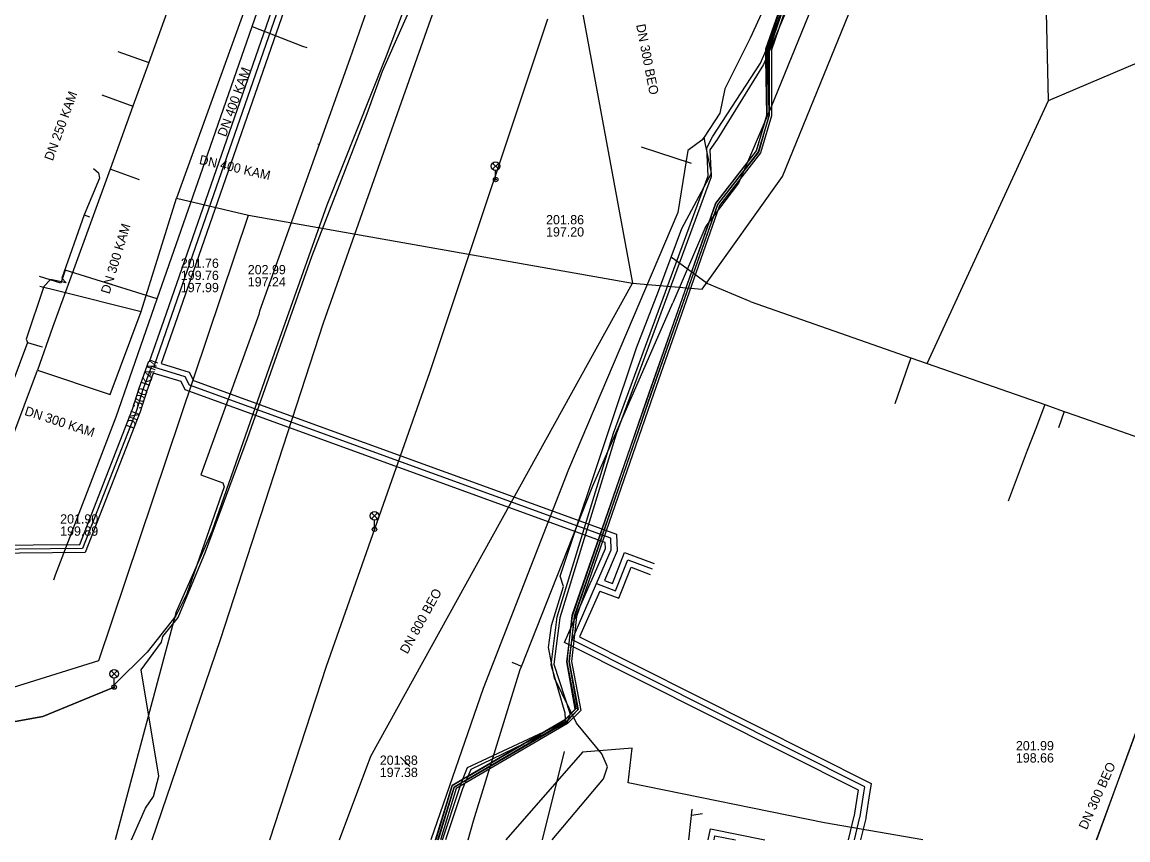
# Model space of a CAD drawing. Extents: x -598932 to -598196, y -1162210 to -1161504.
# Drawn here: x -598647.1 to -598551.8, y -1162207 to -1162136.5 of the extents above; entities that cross this region are included whole.
import ezdxf

# ---------------------------------------------------------------- set-up
doc = ezdxf.new("R2010")
doc.units = 0
for name, color, linetype in [('Vrstva 1', 7, 'Continuous'), ('Vrstva 12', 7, 'Continuous'), ('Vrstva 14', 7, 'Continuous'), ('Vrstva 25', 7, 'Continuous'), ('Vrstva 26', 7, 'Continuous'), ('Vrstva 33', 7, 'Continuous'), ('Vrstva 4', 7, 'Continuous'), ('Vrstva 42', 7, 'Continuous'), ('Vrstva 44', 7, 'Continuous'), ('Vrstva 53', 7, 'Continuous'), ('Vrstva 55', 7, 'Continuous'), ('Vrstva 58', 7, 'Continuous'), ('Vrstva 9', 7, 'Continuous')]:
    doc.layers.add(name, color=color, linetype=linetype)

msp = doc.modelspace()

# ---------------------------------------------------------------- linework, layer by layer
at = {"layer": 'Vrstva 1'}
for p, q in [((-598599.03, -1162134.42), (-598594.47, -1162159.01)), ((-598599.027, -1162134.423), (-598594.47, -1162159.01)), ((-598589.4, -1162148.69), (-598593.72, -1162147.3)), ((-598617.02, -1162199.746), (-598594.47, -1162159.01)), ((-598617.02, -1162199.75), (-598594.47, -1162159.01)), ((-598619.723, -1162206.96), (-598617.02, -1162199.75)), ((-598619.723, -1162206.96), (-598617.02, -1162199.75)), ((-598619.723, -1162206.96), (-598617.02, -1162199.75)), ((-598613.67, -1162200.65), (-598614.45, -1162199.84)), ((-598600.37, -1162199.35), (-598602.252, -1162206.96)), ((-598589.37, -1162204.32), (-598589.653, -1162206.96)), ((-598589.4, -1162204.84), (-598588.45, -1162204.7))]:
    msp.add_line(p, q, dxfattribs=at)
at = {"layer": 'Vrstva 12'}
for p, q in [((-598558.659, -1162143.26), (-598558.872, -1162133.76)), ((-598558.659, -1162143.26), (-598547.642, -1162138.579)), ((-598569.119, -1162165.913), (-598558.659, -1162143.26)), ((-598588.22, -1162146.91), (-598588.32, -1162146.42)), ((-598591.14, -1162156.76), (-598590.22, -1162154.29)), ((-598584.36, -1162160.58), (-598570.51, -1162165.42)), ((-598570.51, -1162165.42), (-598571.9, -1162169.4)), ((-598570.51, -1162165.42), (-598569.119, -1162165.913)), ((-598569.119, -1162165.913), (-598558.98, -1162169.46)), ((-598558.98, -1162169.46), (-598559.702, -1162171.367)), ((-598558.98, -1162169.46), (-598557.3, -1162170.05)), ((-598557.3, -1162170.05), (-598557.8, -1162171.46)), ((-598555.72, -1162170.6), (-598548.21, -1162173.23)), ((-598559.702, -1162171.367), (-598560.493, -1162173.405)), ((-598560.493, -1162173.405), (-598562.125, -1162177.779))]:
    msp.add_line(p, q, dxfattribs=at)
for points in [[(-598564.12, -1162088.67), (-598581.15, -1162130.92), (-598584.34, -1162137.89), (-598586.52, -1162142.25), (-598586.97, -1162144.37), (-598588.32, -1162146.42)], [(-598588.32, -1162146.42), (-598588.5, -1162146.68), (-598589.73, -1162147.56), (-598590.59, -1162152.91), (-598599.99, -1162175.05), (-598607.33, -1162193.91), (-598611.862, -1162206.96)], [(-598590.22, -1162154.29), (-598587.68, -1162149.53), (-598588.22, -1162146.91)], [(-598596.39, -1162171.26), (-598594.15, -1162164.58), (-598592.24, -1162159.7), (-598591.14, -1162156.76)], [(-598584.36, -1162160.58), (-598588.06, -1162159.04), (-598591.14, -1162156.76)], [(-598557.3, -1162170.05), (-598556.312, -1162170.394), (-598555.72, -1162170.6)], [(-598601.73, -1162190.39), (-598601.45, -1162188.5), (-598600.43, -1162185.14), (-598600.72, -1162184.23), (-598596.39, -1162171.26)], [(-598543.01, -1162175.29), (-598543.1, -1162175.61), (-598554.511, -1162206.96)], [(-598601.404, -1162206.96), (-598596.99, -1162201.69), (-598596.64, -1162200.68), (-598597.13, -1162199.54), (-598599.3, -1162196.9), (-598601.2, -1162193.04), (-598601.73, -1162190.39)]]:
    msp.add_lwpolyline(points, dxfattribs=at)
at = {"layer": 'Vrstva 14'}
for p, q in [((-598604.35, -1162191.89), (-598604.846, -1162191.681)), ((-598604.045, -1162192.016), (-598604.35, -1162191.89))]:
    msp.add_line(p, q, dxfattribs=at)
for points in [[(-598644.33, -1162184.57), (-598644.18, -1162184.13), (-598638.95, -1162170.52), (-598635.41, -1162160.34), (-598631.28, -1162148.51), (-598627.24, -1162136.89), (-598622.28, -1162122.66), (-598619.58, -1162114.82), (-598618.34, -1162111.2), (-598616.83, -1162107.09), (-598616.56, -1162106.45), (-598613.65, -1162097.83), (-598610.8, -1162090.29), (-598610.7, -1162090), (-598610.57, -1162089.6)], [(-598564.409, -1162099.249), (-598565.028, -1162100.748), (-598571.148, -1162115.82), (-598576.14, -1162128.127), (-598576.752, -1162129.574), (-598582.543, -1162143.824), (-598585.362, -1162150.375), (-598588.164, -1162154.078), (-598591.021, -1162160.688)], [(-598627.24, -1162136.89), (-598622.89, -1162138.58), (-598622.52, -1162138.7)], [(-598635.41, -1162160.34), (-598643.344, -1162157.87), (-598643.714, -1162159.012), (-598645.55, -1162158.44)], [(-598608.626, -1162206.96), (-598608.18, -1162205.33), (-598604.15, -1162192.28), (-598604.045, -1162192.016), (-598597.9, -1162176.46), (-598591.021, -1162160.688)]]:
    msp.add_lwpolyline(points, dxfattribs=at)
at = {"layer": 'Vrstva 25'}
for points in [[(-598635.714, -1162166.241), (-598634.381, -1162162.409), (-598634.38, -1162162.406), (-598613.829, -1162103.32), (-598624.234, -1162099.93)], [(-598635.714, -1162166.241), (-598635.92, -1162166.167), (-598636.647, -1162168.163), (-598637.21, -1162169.971), (-598641.849, -1162181.867), (-598650.127, -1162181.931), (-598683.649, -1162183.117)], [(-598597.574, -1162184.887), (-598596.314, -1162181.963), (-598596.342, -1162180.979), (-598632.642, -1162167.789), (-598633.001, -1162167.072), (-598635.714, -1162166.241)], [(-598597.574, -1162184.887), (-598595.933, -1162185.508), (-598594.875, -1162182.83), (-598592.782, -1162183.618)], [(-598574.561, -1162202.896), (-598574.475, -1162202.385), (-598599.692, -1162189.716), (-598597.574, -1162184.887)], [(-598575.365, -1162206.96), (-598574.892, -1162205.015), (-598574.88, -1162204.939), (-598574.561, -1162202.896)], [(-598587.457, -1162206.96), (-598587.382, -1162206.608), (-598585.622, -1162206.96)]]:
    msp.add_lwpolyline(points, dxfattribs=at)
at = {"layer": 'Vrstva 26'}
for points in [[(-598624.079, -1162099.455), (-598613.189, -1162103.003), (-598633.909, -1162162.573), (-598635.071, -1162165.915)], [(-598636.07, -1162165.741), (-598634.853, -1162162.244), (-598614.469, -1162103.637), (-598624.389, -1162100.405)], [(-598683.661, -1162182.767), (-598650.135, -1162181.581), (-598642.089, -1162181.519), (-598637.541, -1162169.855), (-598636.979, -1162168.051), (-598636.13, -1162165.72), (-598636.07, -1162165.741)], [(-598635.071, -1162165.915), (-598632.65, -1162166.657), (-598632.284, -1162167.387), (-598595.852, -1162180.625), (-598595.811, -1162182.059), (-598596.908, -1162184.605)], [(-598635.76, -1162166.75), (-598636.315, -1162168.275), (-598636.879, -1162170.087), (-598641.609, -1162182.215), (-598650.119, -1162182.281), (-598683.636, -1162183.467)], [(-598598.033, -1162184.689), (-598596.817, -1162181.867), (-598596.832, -1162181.333), (-598633, -1162168.191), (-598633.352, -1162167.487), (-598635.76, -1162166.75)], [(-598596.908, -1162184.605), (-598596.217, -1162184.866), (-598595.159, -1162182.189), (-598592.606, -1162183.15)], [(-598597.307, -1162185.523), (-598595.649, -1162186.15), (-598594.591, -1162183.471), (-598592.958, -1162184.086)], [(-598575.054, -1162202.813), (-598575.029, -1162202.666), (-598600.341, -1162189.95), (-598598.032, -1162184.686)], [(-598597.307, -1162185.523), (-598599.043, -1162189.482), (-598573.921, -1162202.104), (-598574.068, -1162202.979)], [(-598575.879, -1162206.96), (-598575.383, -1162204.917), (-598575.374, -1162204.861), (-598575.055, -1162202.819)], [(-598574.067, -1162202.973), (-598574.386, -1162205.017), (-598574.401, -1162205.113), (-598574.85, -1162206.96)], [(-598587.969, -1162206.96), (-598587.768, -1162206.021), (-598583.076, -1162206.96)]]:
    msp.add_lwpolyline(points, dxfattribs=at)
at = {"layer": 'Vrstva 33'}
for p, q in [((-598606.535, -1162148.655), (-598606.005, -1162149.185)), ((-598606.535, -1162149.185), (-598606.005, -1162148.655)), ((-598606.27, -1162150.07), (-598606.27, -1162149.295)), ((-598616.965, -1162178.785), (-598616.435, -1162179.315)), ((-598616.965, -1162179.315), (-598616.435, -1162178.785)), ((-598616.7, -1162180.2), (-598616.7, -1162179.425)), ((-598639.385, -1162192.385), (-598638.855, -1162192.915)), ((-598639.385, -1162192.915), (-598638.855, -1162192.385)), ((-598639.12, -1162193.8), (-598639.12, -1162193.025))]:
    msp.add_line(p, q, dxfattribs=at)
for centre, radius in [((-598606.27, -1162148.92), 0.375), ((-598606.27, -1162150.07), 0.19), ((-598606.27, -1162150.07), 0.05), ((-598616.7, -1162179.05), 0.375), ((-598616.7, -1162180.2), 0.19), ((-598616.7, -1162180.2), 0.05), ((-598639.12, -1162192.65), 0.375), ((-598639.12, -1162193.8), 0.19), ((-598639.12, -1162193.8), 0.05)]:
    msp.add_circle(centre, radius, dxfattribs=at)
at = {"layer": 'Vrstva 42'}
msp.add_line((-598633.77, -1162187.31), (-598639.028, -1162206.96), dxfattribs=at)
for points in [[(-598587.25, -1162051.43), (-598590.34, -1162055.11), (-598589.81, -1162057.67), (-598592.26, -1162064.33), (-598592.83, -1162066.93), (-598592.96, -1162069.47), (-598592.36, -1162074.22), (-598595.78, -1162083.76), (-598600.67, -1162097.79), (-598605.47, -1162112.02), (-598610.59, -1162125.88), (-598615.71, -1162139.45), (-598620.8, -1162152.27), (-598625.98, -1162166.85), (-598630.7, -1162180.39), (-598633.77, -1162187.31)], [(-598637.628, -1162206.96), (-598636.43, -1162204.24), (-598635.74, -1162203.22), (-598635.28, -1162201.48), (-598636.8, -1162192.31), (-598635.05, -1162189.92), (-598634.93, -1162189.45), (-598633.61, -1162187.8), (-598631.25, -1162182.14), (-598627.64, -1162172.38), (-598622.09, -1162156.7), (-598617.33, -1162144.38), (-598616, -1162140.73), (-598612.52, -1162132.81), (-598610.5, -1162129.53), (-598603.32, -1162108.9), (-598603.03, -1162105.32), (-598600.08, -1162095.77), (-598597.82, -1162088.64), (-598597.39, -1162087.61), (-598597.12, -1162086.56), (-598595.92, -1162082.91)], [(-598637.628, -1162206.96), (-598636.43, -1162204.24), (-598635.74, -1162203.22), (-598635.28, -1162201.48), (-598636.8, -1162192.31), (-598635.05, -1162189.92), (-598634.93, -1162189.45), (-598633.61, -1162187.8), (-598631.25, -1162182.14), (-598627.64, -1162172.38), (-598622.09, -1162156.7), (-598617.33, -1162144.38), (-598616, -1162140.73), (-598612.52, -1162132.81), (-598610.5, -1162129.53), (-598603.32, -1162108.9), (-598603.03, -1162105.32), (-598600.08, -1162095.77), (-598595.92, -1162082.91)]]:
    msp.add_lwpolyline(points, dxfattribs=at)
at = {"layer": 'Vrstva 44'}
for points in [[(-598588.08, -1162147.33), (-598587.597, -1162146.385), (-598583.448, -1162140.039), (-598583.007, -1162138.994), (-598582.091, -1162136.821), (-598576.501, -1162123.564), (-598567.689, -1162102.217), (-598562.853, -1162089.678), (-598563.332, -1162088.466)], [(-598563.067, -1162088.389), (-598562.504, -1162089.671), (-598567.429, -1162102.258), (-598576.271, -1162123.709), (-598582.804, -1162139.257), (-598582.996, -1162139.715), (-598583.188, -1162140.172), (-598587.178, -1162146.613), (-598587.83, -1162147.52)], [(-598611.455, -1162206.96), (-598610.004, -1162202.273), (-598609.085, -1162201.739), (-598608.659, -1162201.492), (-598603.83, -1162198.686), (-598601.685, -1162197.44), (-598600.293, -1162196.631), (-598600.255, -1162196.59), (-598599.887, -1162196.194), (-598599.417, -1162195.688), (-598600.131, -1162191.613), (-598599.648, -1162187.647), (-598593.054, -1162168.447), (-598587.309, -1162152.141), (-598583.791, -1162147.614), (-598582.92, -1162144.527), (-598582.996, -1162139.715), (-598583.007, -1162138.994), (-598583.01, -1162138.824), (-598578.914, -1162127.225), (-598576.641, -1162121.482), (-598575.191, -1162117.929)], [(-598611.245, -1162206.96), (-598609.836, -1162202.407), (-598609.197, -1162202.036), (-598608.794, -1162201.802), (-598601.48, -1162197.552), (-598600.167, -1162196.789), (-598600.065, -1162196.68), (-598599.203, -1162195.752), (-598599.929, -1162191.607), (-598599.452, -1162187.693), (-598592.866, -1162168.513), (-598587.131, -1162152.239), (-598583.609, -1162147.706), (-598582.72, -1162144.553), (-598582.804, -1162139.257), (-598582.81, -1162138.856), (-598582.091, -1162136.821), (-598578.726, -1162127.295)], [(-598610.843, -1162206.96), (-598609.38, -1162202.52), (-598609.197, -1162202.036), (-598609.085, -1162201.739), (-598608.697, -1162200.713), (-598601.685, -1162197.44), (-598600.25, -1162196.77), (-598600.255, -1162196.59), (-598600.27, -1162196.04), (-598601.48, -1162191.87), (-598600.96, -1162187.74), (-598596.11, -1162171.92), (-598587.98, -1162149.75), (-598588.08, -1162147.33)], [(-598587.83, -1162147.52), (-598587.7, -1162149.85), (-598595.9, -1162172.02), (-598600.75, -1162187.83), (-598601.25, -1162191.81), (-598599.86, -1162196.12), (-598599.887, -1162196.194), (-598600.065, -1162196.68), (-598600.15, -1162196.91), (-598601.48, -1162197.552), (-598603.83, -1162198.686), (-598608.397, -1162200.89), (-598608.659, -1162201.492), (-598608.794, -1162201.802), (-598609.12, -1162202.55), (-598610.587, -1162206.96)]]:
    msp.add_lwpolyline(points, dxfattribs=at)
at = {"layer": 'Vrstva 53'}
msp.add_lwpolyline([(-598554.51, -1162206.96), (-598542.96, -1162175.53), (-598548.332, -1162172.932)], dxfattribs=at)
at = {"layer": 'Vrstva 55'}
for p, q in [((-598611.18, -1162164.448), (-598601.774, -1162136.233)), ((-598621.46, -1162147.07), (-598621.58, -1162147.03)), ((-598641.72, -1162153.12), (-598641.26, -1162153.3)), ((-598646.6, -1162164.1), (-598648.66, -1162169.65)), ((-598611.728, -1162166.093), (-598611.18, -1162164.448))]:
    msp.add_line(p, q, dxfattribs=at)
for points in [[(-598635.847, -1162206.96), (-598629.97, -1162189.7), (-598621.09, -1162162.42), (-598598.1, -1162097.33), (-598589.15, -1162070.89), (-598592.61, -1162069.46), (-598587.52, -1162054.61), (-598584.27, -1162048.71), (-598581.62, -1162049.12), (-598567.59, -1162009.46), (-598573.28, -1162007.22), (-598571.851, -1162001.315), (-598576.64, -1161997.21), (-598590.4, -1161991.37), (-598599.45, -1161987.03), (-598615.67, -1161976.28), (-598632.44, -1161961.96), (-598678.26, -1161917.47), (-598684.987, -1161911.745), (-598688.029, -1161910.224), (-598691.806, -1161909.122), (-598694.533, -1161909.122), (-598697.86, -1161910.3), (-598707.4, -1161922.62)], [(-598616.41, -1162132.77), (-598618.82, -1162139.67), (-598621.46, -1162147.07)], [(-598621.46, -1162147.07), (-598626.6, -1162161.42), (-598626.67, -1162161.69), (-598631.65, -1162175.51)], [(-598640.9, -1162149.12), (-598640.47, -1162149.5), (-598640.39, -1162149.95), (-598641.72, -1162153.12)], [(-598641.72, -1162153.12), (-598643.64, -1162158.57), (-598643.27, -1162158.96), (-598644.62, -1162158.68), (-598645.17, -1162159.28), (-598646.69, -1162163.82), (-598646.6, -1162164.1)], [(-598646.6, -1162164.1), (-598645.53, -1162164.44), (-598645.3, -1162164.49)], [(-598625.704, -1162206.96), (-598620.83, -1162191.99), (-598611.93, -1162166.7), (-598611.728, -1162166.093)], [(-598631.65, -1162175.51), (-598629.75, -1162176.19), (-598629.64, -1162176.55), (-598632.87, -1162185.75), (-598633.8, -1162187.66), (-598636.28, -1162190.78), (-598639.16, -1162193.63), (-598639.36, -1162193.7)], [(-598734.15, -1162190.57), (-598723.421, -1162192.088), (-598710.96, -1162193.2), (-598687.278, -1162196.351), (-598662.25, -1162199.4), (-598645.273, -1162196.322), (-598639.12, -1162193.8), (-598645.273, -1162196.322), (-598662.25, -1162199.4), (-598687.278, -1162196.351), (-598710.96, -1162193.2)], [(-598594.51, -1162199.05), (-598598.8, -1162199.4), (-598605.389, -1162206.96)], [(-598569.474, -1162206.96), (-598577.94, -1162205.49), (-598594.86, -1162202.05), (-598594.51, -1162199.05)]]:
    msp.add_lwpolyline(points, dxfattribs=at)
at = {"layer": 'Vrstva 58'}
for points in [[(-598564.189, -1162084.364), (-598569.319, -1162099.564), (-598571.135, -1162104.591), (-598571.625, -1162108.002), (-598574.427, -1162116.01), (-598578.938, -1162127.21), (-598582.91, -1162138.837), (-598582.91, -1162144.521), (-598583.831, -1162147.597), (-598587.348, -1162152.123), (-598593.059, -1162168.444), (-598599.696, -1162187.635), (-598600.152, -1162191.608), (-598599.367, -1162195.672), (-598600.322, -1162196.61), (-598610.009, -1162202.277), (-598611.422, -1162206.96)], [(-598564.189, -1162084.364), (-598569.319, -1162099.564), (-598571.135, -1162104.591), (-598571.625, -1162108.002), (-598574.427, -1162116.01), (-598578.938, -1162127.21), (-598582.91, -1162138.837), (-598582.91, -1162144.521), (-598583.831, -1162147.597), (-598587.348, -1162152.123), (-598593.059, -1162168.444), (-598599.696, -1162187.635), (-598600.152, -1162191.608), (-598599.367, -1162195.672), (-598600.322, -1162196.61), (-598610.009, -1162202.277), (-598611.422, -1162206.96)], [(-598564, -1162084.43), (-598569.13, -1162099.63), (-598570.94, -1162104.64), (-598571.43, -1162108.05), (-598574.24, -1162116.08), (-598578.75, -1162127.28), (-598582.71, -1162138.87), (-598582.71, -1162144.55), (-598583.65, -1162147.69), (-598587.17, -1162152.22), (-598592.87, -1162168.51), (-598599.5, -1162187.68), (-598599.95, -1162191.6), (-598599.15, -1162195.74), (-598600.2, -1162196.77), (-598609.84, -1162202.41), (-598611.213, -1162206.96)], [(-598564, -1162084.43), (-598569.13, -1162099.63), (-598570.94, -1162104.64), (-598571.43, -1162108.05), (-598574.24, -1162116.08), (-598578.75, -1162127.28), (-598582.71, -1162138.87), (-598582.71, -1162144.55), (-598583.65, -1162147.69), (-598587.17, -1162152.22), (-598592.87, -1162168.51), (-598599.5, -1162187.68), (-598599.95, -1162191.6), (-598599.15, -1162195.74), (-598600.2, -1162196.77), (-598609.84, -1162202.41), (-598611.213, -1162206.96)], [(-598563.811, -1162084.496), (-598568.941, -1162099.696), (-598570.745, -1162104.689), (-598571.235, -1162108.098), (-598574.053, -1162116.15), (-598578.562, -1162127.35), (-598582.51, -1162138.903), (-598582.51, -1162144.579), (-598583.469, -1162147.783), (-598586.992, -1162152.317), (-598592.681, -1162168.576), (-598599.304, -1162187.725), (-598599.748, -1162191.592), (-598598.933, -1162195.808), (-598600.078, -1162196.93), (-598609.671, -1162202.543), (-598611.004, -1162206.96)]]:
    msp.add_lwpolyline(points, dxfattribs=at)
at = {"layer": 'Vrstva 9'}
for p, q in [((-598581.57, -1162149.82), (-598560.23, -1162097.53)), ((-598638.817, -1162139.039), (-598636.149, -1162140.006)), ((-598640.173, -1162142.78), (-598637.506, -1162143.747)), ((-598636.935, -1162150.103), (-598639.477, -1162149.181)), ((-598588.48, -1162159.51), (-598581.57, -1162149.82)), ((-598636.8, -1162161.43), (-598633.76, -1162151.67)), ((-598633.76, -1162151.67), (-598627.54, -1162153.14)), ((-598640.45, -1162191.51), (-598627.54, -1162153.14)), ((-598627.54, -1162153.14), (-598594.47, -1162159.01)), ((-598645.514, -1162159.273), (-598644, -1162159.63)), ((-598644, -1162159.63), (-598636.8, -1162161.43)), ((-598594.47, -1162159.01), (-598588.48, -1162159.51)), ((-598639.47, -1162168.59), (-598636.8, -1162161.43)), ((-598644.42, -1162162.81), (-598645.73, -1162166.51)), ((-598649.37, -1162176.22), (-598645.73, -1162166.51)), ((-598645.73, -1162166.51), (-598639.47, -1162168.59)), ((-598652.978, -1162195.422), (-598640.45, -1162191.51))]:
    msp.add_line(p, q, dxfattribs=at)
for points in [[(-598632.9, -1162131.05), (-598634.069, -1162134.272), (-598634.321, -1162134.967), (-598636.149, -1162140.006), (-598637.506, -1162143.747), (-598639.477, -1162149.181), (-598644.42, -1162162.81)], [(-598626.44, -1162131.43), (-598627.664, -1162134.815), (-598628.215, -1162136.338), (-598633.76, -1162151.67)]]:
    msp.add_lwpolyline(points, dxfattribs=at)

# ---------------------------------------------------------------- texts
at = {"layer": 'Vrstva 12'}
for s, rotation, p in [('DN 400 KAM', 70, (-598629.502, -1162146.454)), ('DN 250 KAM', 70, (-598644.416, -1162148.52)), ('DN 400 KAM', 347, (-598631.851, -1162148.724)), ('DN 300 KAM', 73, (-598639.527, -1162159.989)), ('DN 300 KAM', 70, (-598637.44, -1162171.624)), ('DN 300 KAM', 342, (-598646.898, -1162170.342))]:
    msp.add_text(s, height=0.8, rotation=rotation, dxfattribs=at).set_placement(p)
for s, p in [('201.86', (-598601.926, -1162153.934)), ('197.20', (-598601.926, -1162154.984)), ('201.76', (-598633.381, -1162157.681)), ('199.76', (-598633.381, -1162158.731)), ('202.99', (-598627.615, -1162158.237)), ('197.24', (-598627.615, -1162159.287)), ('197.99', (-598633.381, -1162159.781)), ('201.90', (-598643.77, -1162179.711)), ('199.89', (-598643.77, -1162180.761))]:
    msp.add_text(s, height=0.8, dxfattribs=at).set_placement(p)
at = {"layer": 'Vrstva 4'}
for s, rotation, p in [('DN 300 BEO', 281, (-598594.176, -1162136.756)), ('DN 800 BEO', 61, (-598613.868, -1162191.004)), ('DN 300 BEO', 66, (-598555.362, -1162206.142))]:
    msp.add_text(s, height=0.8, rotation=rotation, dxfattribs=at).set_placement(p)
for s, p in [('201.99', (-598561.463, -1162199.246)), ('201.88', (-598616.244, -1162200.493)), ('198.66', (-598561.463, -1162200.296)), ('197.38', (-598616.244, -1162201.543))]:
    msp.add_text(s, height=0.8, dxfattribs=at).set_placement(p)

doc.saveas('drawing.dxf')
